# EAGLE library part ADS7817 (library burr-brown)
12-Bit Diff. Input Micro Power Sampling ADC
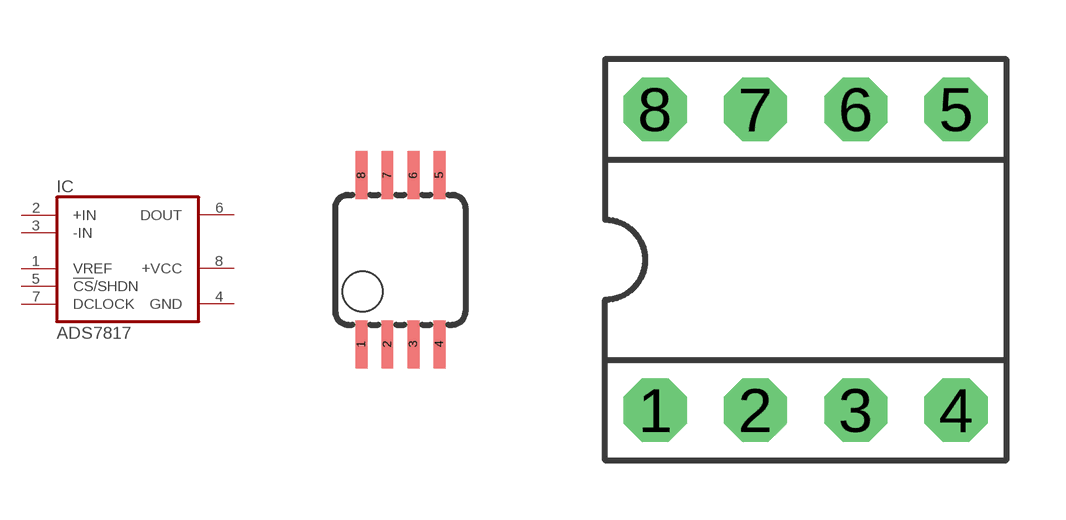
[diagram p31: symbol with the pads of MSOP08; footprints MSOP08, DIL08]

Designator prefix IC

## ADS7817E (MPN: ADS7817E/250G4; OC_FARNELL: unknown; OC_NEWARK: 73K7081)  [MSOP08]
1  VREF  in
2  +IN  in
3  -IN  in
4  GND  pwr
5  !CS!/SHDN  in
6  DOUT  out
7  DCLOCK  in
8  +VCC  pwr

## ADS7817P (OC_FARNELL: unknown; OC_NEWARK: unknown)  [DIL08]
Pads as for MSOP08

## ADS7817U (MF: TEXAS INSTRUMENT CONNECTORS; MPN: ADS7817UC; OC_FARNELL: 1407035; OC_NEWARK: 74C7126)  [SO08-GW]
Pads as for MSOP08

## Footprint MSOP08 (pad centres in mm)
Mini Small Outline Package
smd 0.3 x 1.2: 1 -0.976,-2.113; 2 -0.326,-2.113; 3 0.324,-2.113; 4 0.974,-2.113; 5 0.974,2.112; 6 0.324,2.112; 7 -0.326,2.112; 8 -0.976,2.112

## Footprint DIL08 (pad centres in mm)
Dual In Line
drill 0.813 pad 1.6 octagon: 1 -3.81,-3.81; 2 -1.27,-3.81; 3 1.27,-3.81; 4 3.81,-3.81; 5 3.81,3.81; 6 1.27,3.81; 7 -1.27,3.81; 8 -3.81,3.81

## Footprint SO08-GW (pad centres in mm)
Small Outline Package, gull wing
smd 0.762 x 2.21: 1 -3.81,-4.318; 2 -1.27,-4.318; 3 1.27,-4.318; 4 3.81,-4.318; 5 3.81,4.318; 6 1.27,4.318; 7 -1.27,4.318; 8 -3.81,4.318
